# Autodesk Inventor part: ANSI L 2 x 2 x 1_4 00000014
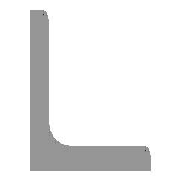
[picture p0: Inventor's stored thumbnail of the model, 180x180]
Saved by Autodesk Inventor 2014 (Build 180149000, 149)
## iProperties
IsCustomPart: 1
Created: 2007-02
Part Number: ANSI L 2 x 2 x 1_4 00000014
Material: Steel, Mild
Document SubType Name: Modeling
Standard: AISC
Designer: Autodesk, Inc.
Size Designation: L 2 x 2 x 1/4
Stock Number: L 2 x 2 x 1/4
Density: 7.86 g/cm^3
Description: Angle Steel
Standards Organization: ANSI
Language: en-US
Categories: <MemberInstance><Categories><Category DisplayName="Structural Shapes" InternalName="089c4875-fa83-4c05-b084-43b9cc11f5ed" Mnemonic="GRDR"><CategoryParameter Dis
Mass: 2878.9 g
Surface Area: 1206.61 cm^2
Volume: 366.272 cm^3
Appearance: Steel
_FrameMemberDoc: Frame Member File
_Version: 15.0.0
_CCFamilyMember: 11
_CCFamilyDisplayName: ANSI L (Equal angles) - Angle Steel
G_L: 24.393 in
G_W: 2.000 in
G_H: 2.000 in
+0C829B48-3858-41F8-B33C-9FF71A575EB4+CUTDETAIL1: Miter 45.00 deg
+7384AA33-C70C-4C96-BA3D-BC0A1F3EFC07+CUTDETAIL2: Cut
Author: Autodesk, Inc.
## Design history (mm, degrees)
node "Start plane"
node "End plane"
sketch "Sketch"
  geometry: L1 (50.8, 0)-(0, 0); L2 (0, 0)-(0, 50.8); L3 (0, 50.8)-(3.302, 50.8); L4 (6.35, 47.752)-(6.35, 12.7); L5 (12.7, 6.35)-(47.752, 6.35); L6 (50.8, 3.302)-(50.8, 0); L7 (0, -11.041)-(0, 31.538); L8 (-11.041, 0)-(31.538, 0); L9 (0, 63.926)-(0, -23.536) reference; L10 (-23.536, 0)-(63.926, 0) reference; A1 r 6.35 centre (12.7, 12.7) between (6.35, 12.7) and (12.7, 6.35); A2 r 3.048 centre (3.302, 47.752) between (6.35, 47.752) and (3.302, 50.8); A3 r 3.048 centre (47.752, 3.302) between (50.8, 3.302) and (47.752, 6.35); 3 further points
  constraints: 16 end point, 6 point on circle, 6 point on line, 6 tangent, 4 parallel, 3 centre point, 2 collinear, 1 equal radius, 1 horizontal, 1 perpendicular
  dimensions: "d0" = 50.8 distance between parallel lines of L6 L2 (= G_H); "d1" = 50.8 distance between parallel lines of L3 L1 (= G_H); "d2" = 6.35 distance between parallel lines of L2 L4 (= G_T); "d3" = 6.35 distance between parallel lines of L1 L5 (= G_T); "d10" = 0 distance between parallel lines of L7 L2 (computed from ex); "d11" = 0 distance between parallel lines of L8 L1 (computed from d10); "d14" = 6.35 radius of A1 (= G_IR); "d15" = 3.048 radius of A2 (= G_ER)
extrude "Body" new body sketch "Sketch" stored distance "d4" = 619.5695 (= G_L); taper "d5" = 0 deg
node "Driven Length"
  sketch "Sketch4"
    geometry: L1 (0, 0)-(10, 0) reference
    constraints: 2 end point, 1 horizontal
  workplane "Work Plane5"
  sketch "Sketch5"
    geometry: L1 (-2, 6.35)-(12, 6.35) reference; L2 (-2, 625.919)-(12, 625.919) reference
    dimensions: "d19" = 619.5695 distance between parallel lines of L1 L2 (derived)
workplane "Work Plane3"
split "Split1"
workplane "Work Plane4"
split "Split2"
sketch "Sketch3"
  geometry: C1 r 8.331 at (263.97, 34.925) reference; C2 r 8.331 at (581.47, 34.925) reference
  constraints: 2 centre point, 4 other
extrude "Extrusion2" cut sketch "Sketch3" stored distance "d16" = 25.4; taper "d17" = 0 deg
body "Solid1"
other parameters: "G_H" = 50.8 [user parameter; used in 2 equation terms], "G_T" = 6.35 [user parameter; used in 2 equation terms], "G_ER" = 3.048 [user parameter; used in 1 equation term], "G_IR" = 6.35 [user parameter; used in 1 equation term], "G_L" = 619.5695 (= d19) [user parameter; used in 1 equation term], "ex" = 0 [user parameter; used in 1 equation term], "G_OFFSET_START" = -6.35 [user parameter; used in 1 equation term], "G_OFFSET_END" = 0 [user parameter; used in 1 equation term], "d12" = 6.35 (= -G_OFFSET_START), "d13" = 625.9195 (= G_OFFSET_END + B_L), "B_L" = 625.9195 [user parameter; used in 1 equation term], "d18" = 90 deg
